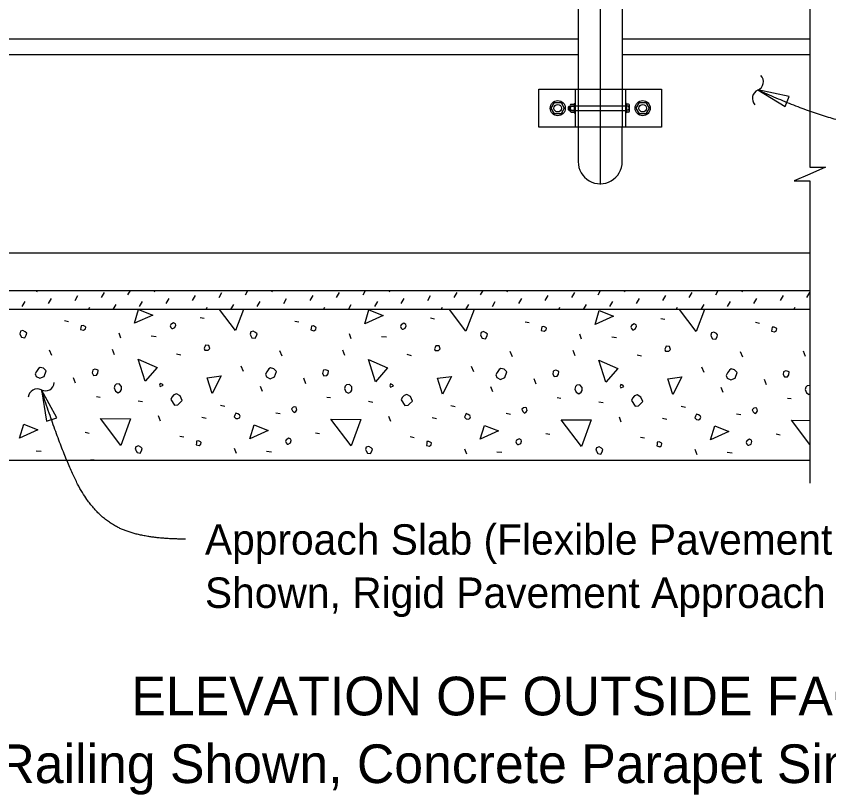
# Model space of a CAD drawing. Extents: x 0 to 41.1, y 0 to 25.9.
# Drawn here: x 10.75 to 16.13, y 11.22 to 16.37 of the extents above; entities that cross this region are included whole.
import ezdxf

# ---------------------------------------------------------------- set-up
doc = ezdxf.new("R2010")
doc.units = 0
for name, color, linetype in [('CL_Major', 7, 'Continuous'), ('Dimension', 7, 'Continuous'), ('Miscellaneous', 7, 'Continuous'), ('SteelMisc', 7, 'Continuous'), ('SteelMisc_h', 7, 'Continuous'), ('SupstrConc', 7, 'Continuous'), ('SupstrConc_h', 7, 'Continuous')]:
    doc.layers.add(name, color=color, linetype=linetype)

msp = doc.modelspace()

# ---------------------------------------------------------------- linework, layer by layer
at = {"layer": 'CL_Major'}
msp.add_line((14.615, 25.0052), (14.615, 15.2584), dxfattribs=at)
at = {"layer": 'Dimension'}
msp.add_lwpolyline([(16.002, 17.2246), (16.002, 15.3737), (16.1053, 15.3737), (16.002, 15.3287), (15.8987, 15.2837), (16.002, 15.2837), (16.002, 13.2829)], dxfattribs=at)
for points in [[(15.6583, 15.8852), (15.8392, 15.7761), (15.865, 15.8418)], [(10.9179, 13.9006), (10.9525, 13.6922), (11.0192, 13.7152)]]:
    msp.add_lwpolyline(points, close=True, dxfattribs=at)
for centre, start, end in [((15.6351, 15.9394), 292.7091, 44.4364), ((15.6811, 15.8294), 112.7091, 224.4364), ((10.944, 13.9535), 243.2317, 354.9589), ((10.8904, 13.847), 63.2317, 174.9589)]:
    msp.add_arc(centre, 0.0596, start, end, dxfattribs=at)
for points in [[(16.9853, 15.6282), (16.9154, 15.6282), (16.2159, 15.6282), (15.6583, 15.8852)], [(11.8715, 12.9128), (11.6062, 12.9128), (11.3076, 13.0373), (11.092, 13.3693), (10.9179, 13.9005)]]:
    msp.add_open_spline(points, degree=2, dxfattribs=at)
at = {"layer": 'Miscellaneous'}
for p, q in [((14.4075, 15.7575), (14.4075, 15.7696)), ((14.4132, 15.7575), (14.4132, 15.7696)), ((10.8876, 14.5495), (10.8924, 14.5578)), ((11.1404, 14.4912), (11.1599, 14.5248)), ((11.3154, 14.5106), (11.3349, 14.5442)), ((11.4904, 14.5301), (11.5065, 14.5578)), ((11.6655, 14.5495), (11.6703, 14.5578)), ((11.9182, 14.4912), (11.9377, 14.5248)), ((12.0933, 14.5106), (12.1127, 14.5442)), ((12.2683, 14.5301), (12.2843, 14.5578)), ((12.4433, 14.5495), (12.4481, 14.5578)), ((12.6961, 14.4912), (12.7155, 14.5248)), ((12.8711, 14.5106), (12.8905, 14.5442)), ((13.0461, 14.5301), (13.0621, 14.5578)), ((13.2211, 14.5495), (13.2259, 14.5578)), ((13.4739, 14.4912), (13.4933, 14.5248)), ((13.6489, 14.5106), (13.6683, 14.5442)), ((13.8239, 14.5301), (13.84, 14.5578)), ((13.9989, 14.5495), (14.0037, 14.5578)), ((14.2517, 14.4912), (14.2711, 14.5248)), ((14.4267, 14.5106), (14.4462, 14.5442)), ((14.6017, 14.5301), (14.6178, 14.5578)), ((14.7767, 14.5495), (14.7815, 14.5578)), ((15.0295, 14.4912), (15.049, 14.5248)), ((15.2045, 14.5106), (15.224, 14.5442)), ((15.3795, 14.5301), (15.3956, 14.5578)), ((15.5545, 14.5495), (15.5593, 14.5578)), ((15.8073, 14.4912), (15.8268, 14.5248)), ((15.9823, 14.5106), (16.0018, 14.5442)), ((10.7904, 14.4523), (10.8099, 14.4859)), ((10.9654, 14.4717), (10.9849, 14.5053)), ((11.3932, 14.4329), (11.4127, 14.4664)), ((11.5682, 14.4523), (11.5877, 14.4859)), ((11.7432, 14.4717), (11.7627, 14.5053)), ((12.171, 14.4329), (12.1905, 14.4664)), ((12.346, 14.4523), (12.3655, 14.4859)), ((12.5211, 14.4717), (12.5405, 14.5053)), ((12.9489, 14.4329), (12.9683, 14.4664)), ((13.1239, 14.4523), (13.1433, 14.4859)), ((13.2989, 14.4717), (13.3183, 14.5053)), ((13.7267, 14.4329), (13.7461, 14.4664)), ((13.9017, 14.4523), (13.9211, 14.4859)), ((14.0767, 14.4717), (14.0961, 14.5053)), ((14.5045, 14.4329), (14.5239, 14.4664)), ((14.6795, 14.4523), (14.6989, 14.4859)), ((14.8545, 14.4717), (14.874, 14.5053)), ((15.2823, 14.4329), (15.3018, 14.4664)), ((15.4573, 14.4523), (15.4768, 14.4859)), ((15.6323, 14.4717), (15.6518, 14.5053)), ((11.2295, 14.4329), (11.2377, 14.447)), ((12.0073, 14.4329), (12.0155, 14.447)), ((12.7851, 14.4329), (12.7933, 14.447)), ((13.5629, 14.4329), (13.5711, 14.447)), ((14.3407, 14.4329), (14.3489, 14.447)), ((15.1186, 14.4329), (15.1267, 14.447)), ((15.8964, 14.4329), (15.9046, 14.447)), ((11.0699, 14.3586), (11.0964, 14.3533)), ((11.9679, 14.3798), (11.9945, 14.3745)), ((12.5937, 14.3551), (12.6202, 14.3498)), ((13.4917, 14.3763), (13.5183, 14.371)), ((15.0156, 14.3728), (15.0421, 14.3674)), ((14.1175, 14.3515), (14.1441, 14.3462)), ((15.6414, 14.348), (15.6679, 14.3427)), ((11.4447, 14.2419), (11.4323, 14.2755)), ((11.6444, 14.2578), (11.6763, 14.2543)), ((12.9685, 14.2384), (12.9561, 14.272)), ((13.1682, 14.2543), (13.2001, 14.2508)), ((14.4923, 14.2349), (14.4799, 14.2685)), ((14.6921, 14.2508), (14.7239, 14.2472)), ((10.9868, 14.127), (10.9727, 14.1624)), ((11.4022, 14.1323), (11.3881, 14.1677)), ((11.8124, 14.1394), (11.8407, 14.1323)), ((12.5106, 14.1235), (12.4965, 14.1589)), ((12.9261, 14.1288), (12.9119, 14.1642)), ((14.0345, 14.12), (14.0203, 14.1553)), ((14.4499, 14.1253), (14.4357, 14.1606)), ((15.5583, 14.1164), (15.5441, 14.1518)), ((15.9737, 14.1217), (15.9596, 14.1571)), ((13.3362, 14.1359), (13.3645, 14.1288)), ((14.86, 14.1323), (14.8883, 14.1253)), ((12.2543, 14.0227), (12.2402, 14.0581)), ((13.7781, 14.0192), (13.764, 14.0546)), ((15.3019, 14.0157), (15.2878, 14.051)), ((11.1442, 13.945), (11.13, 13.9803)), ((12.668, 13.9414), (12.6538, 13.9768)), ((12.3798, 13.8901), (12.3675, 13.9237)), ((14.1918, 13.9379), (14.1776, 13.9732)), ((15.7156, 13.9343), (15.7015, 13.9697)), ((13.9036, 13.8866), (13.8913, 13.9202)), ((15.4275, 13.8831), (15.4151, 13.9167)), ((11.282, 13.8566), (11.3068, 13.853)), ((11.5578, 13.8283), (11.5879, 13.823)), ((12.8059, 13.853), (12.8306, 13.8495)), ((13.0816, 13.8247), (13.1117, 13.8194)), ((14.3297, 13.8495), (14.3544, 13.846)), ((14.6054, 13.8212), (14.6355, 13.8159)), ((15.8535, 13.846), (15.8782, 13.8424)), ((12.1023, 13.8), (12.1306, 13.7929)), ((13.6261, 13.7965), (13.6544, 13.7894)), ((15.1499, 13.7929), (15.1782, 13.7859)), ((11.7063, 13.6939), (11.6939, 13.7275)), ((11.9803, 13.7204), (12.0086, 13.7134)), ((12.4682, 13.7487), (12.4983, 13.7434)), ((13.2301, 13.6904), (13.2177, 13.724)), ((13.5041, 13.7169), (13.5324, 13.7098)), ((13.992, 13.7452), (14.0221, 13.7399)), ((14.7539, 13.6869), (14.7416, 13.7204)), ((15.0279, 13.7134), (15.0562, 13.7063)), ((15.5158, 13.7417), (15.5459, 13.7364)), ((11.2078, 13.6197), (11.2343, 13.6144)), ((12.7316, 13.6161), (12.7581, 13.6108)), ((14.2554, 13.6126), (14.2819, 13.6073)), ((15.7792, 13.6091), (15.8058, 13.6038)), ((11.8336, 13.5949), (11.8601, 13.5896)), ((13.3574, 13.5914), (13.3839, 13.5861)), ((14.8812, 13.5879), (14.9077, 13.5826)), ((10.8843, 13.4977), (10.9161, 13.4942)), ((12.2084, 13.4783), (12.196, 13.5118)), ((12.4081, 13.4942), (12.4399, 13.4906)), ((13.7322, 13.4747), (13.7198, 13.5083)), ((15.256, 13.4712), (15.2436, 13.5048)), ((13.9319, 13.4906), (13.9637, 13.4871)), ((15.4557, 13.4871), (15.4876, 13.4836))]:
    msp.add_line(p, q, dxfattribs=at)
for points in [[(11.5331, 14.3409), (11.5613, 14.4329), (11.655, 14.3957), (11.5331, 14.3409)], [(12.203, 14.2932), (12.0969, 14.4329)], [(12.2552, 14.4329), (12.203, 14.2932)], [(13.0569, 14.3374), (13.0852, 14.4293), (13.1789, 14.3922), (13.0569, 14.3374)], [(13.7269, 14.2897), (13.618, 14.4329)], [(13.7804, 14.4329), (13.7269, 14.2897)], [(14.5807, 14.3339), (14.609, 14.4258), (14.7027, 14.3887), (14.5807, 14.3339)], [(15.2507, 14.2861), (15.1392, 14.4329)], [(15.3055, 14.4329), (15.2507, 14.2861)], [(11.1777, 14.3003), (11.1972, 14.295), (11.2096, 14.3038), (11.2113, 14.3162), (11.2078, 14.3197), (11.1937, 14.3268), (11.1813, 14.325), (11.1795, 14.3126), (11.1777, 14.3003)], [(11.7806, 14.3056), (11.7876, 14.3056), (11.8018, 14.3126), (11.8071, 14.3286), (11.8053, 14.3374), (11.7912, 14.3445), (11.7735, 14.3339), (11.7699, 14.3233), (11.7735, 14.3126), (11.7806, 14.3056)], [(12.7016, 14.2967), (12.721, 14.2914), (12.7334, 14.3003), (12.7351, 14.3126), (12.7316, 14.3162), (12.7175, 14.3233), (12.7051, 14.3215), (12.7033, 14.3091), (12.7016, 14.2967)], [(13.3044, 14.302), (13.3114, 14.302), (13.3256, 14.3091), (13.3309, 14.325), (13.3291, 14.3339), (13.315, 14.3409), (13.2973, 14.3303), (13.2938, 14.3197), (13.2973, 14.3091), (13.3044, 14.302)], [(14.2254, 14.2932), (14.2448, 14.2879), (14.2572, 14.2967), (14.259, 14.3091), (14.2554, 14.3126), (14.2413, 14.3197), (14.2289, 14.3179), (14.2271, 14.3056), (14.2254, 14.2932)], [(14.8282, 14.2985), (14.8353, 14.2985), (14.8494, 14.3056), (14.8547, 14.3215), (14.8529, 14.3303), (14.8388, 14.3374), (14.8211, 14.3268), (14.8176, 14.3162), (14.8211, 14.3056), (14.8282, 14.2985)], [(15.7492, 14.2897), (15.7686, 14.2844), (15.781, 14.2932), (15.7828, 14.3056), (15.7792, 14.3091), (15.7651, 14.3162), (15.7527, 14.3144), (15.751, 14.302), (15.7492, 14.2897)], [(10.7782, 14.2649), (10.7871, 14.249), (10.8083, 14.2455), (10.8171, 14.2614), (10.8207, 14.2755), (10.8118, 14.2844), (10.7959, 14.2932), (10.78, 14.2879), (10.7747, 14.272), (10.7782, 14.2649)], [(12.302, 14.2614), (12.3109, 14.2455), (12.3321, 14.2419), (12.3409, 14.2578), (12.3445, 14.272), (12.3356, 14.2808), (12.3197, 14.2897), (12.3038, 14.2844), (12.2985, 14.2685), (12.302, 14.2614)], [(13.8259, 14.2578), (13.8347, 14.2419), (13.8559, 14.2384), (13.8647, 14.2543), (13.8683, 14.2685), (13.8594, 14.2773), (13.8435, 14.2861), (13.8276, 14.2808), (13.8223, 14.2649), (13.8259, 14.2578)], [(15.3497, 14.2543), (15.3585, 14.2384), (15.3797, 14.2349), (15.3886, 14.2508), (15.3921, 14.2649), (15.3833, 14.2738), (15.3674, 14.2826), (15.3514, 14.2773), (15.3461, 14.2614), (15.3497, 14.2543)], [(11.9998, 14.1642), (12.021, 14.1642), (12.0316, 14.1748), (12.0263, 14.1942), (12.0033, 14.196), (11.9998, 14.1854), (11.9945, 14.1765), (11.9998, 14.1642), (11.9962, 14.1677)], [(13.5236, 14.1606), (13.5448, 14.1606), (13.5554, 14.1712), (13.5501, 14.1907), (13.5271, 14.1924), (13.5236, 14.1818), (13.5183, 14.173), (13.5236, 14.1606), (13.52, 14.1642)], [(15.0474, 14.1571), (15.0686, 14.1571), (15.0792, 14.1677), (15.0739, 14.1871), (15.0509, 14.1889), (15.0474, 14.1783), (15.0421, 14.1695), (15.0474, 14.1571), (15.0438, 14.1606)], [(11.6055, 13.9573), (11.5578, 14.104), (11.6833, 14.0492), (11.6055, 13.9573)], [(13.1294, 13.9538), (13.0816, 14.1005), (13.2071, 14.0457), (13.1294, 13.9538)], [(14.6532, 13.9503), (14.6054, 14.097), (14.731, 14.0422), (14.6532, 13.9503)], [(10.8843, 13.9891), (10.9073, 13.9768), (10.9373, 13.9891), (10.9497, 14.0263), (10.932, 14.0439), (10.909, 14.0492), (10.8984, 14.0422), (10.8861, 14.0227), (10.8772, 14.0068), (10.8843, 13.9891)], [(11.2538, 14.0121), (11.2626, 13.9962), (11.282, 13.998), (11.2909, 14.0104), (11.2926, 14.0298), (11.2803, 14.0351), (11.2714, 14.0369), (11.2608, 14.0333), (11.2573, 14.0298), (11.2538, 14.0121)], [(12.4081, 13.9856), (12.4311, 13.9732), (12.4611, 13.9856), (12.4735, 14.0227), (12.4558, 14.0404), (12.4329, 14.0457), (12.4223, 14.0386), (12.4099, 14.0192), (12.401, 14.0033), (12.4081, 13.9856)], [(12.7776, 14.0086), (12.7864, 13.9927), (12.8059, 13.9944), (12.8147, 14.0068), (12.8165, 14.0263), (12.8041, 14.0316), (12.7952, 14.0333), (12.7846, 14.0298), (12.7811, 14.0263), (12.7776, 14.0086)], [(13.9319, 13.9821), (13.9549, 13.9697), (13.985, 13.9821), (13.9973, 14.0192), (13.9797, 14.0369), (13.9567, 14.0422), (13.9461, 14.0351), (13.9337, 14.0157), (13.9249, 13.9998), (13.9319, 13.9821)], [(14.3014, 14.0051), (14.3102, 13.9891), (14.3297, 13.9909), (14.3385, 14.0033), (14.3403, 14.0227), (14.3279, 14.028), (14.3191, 14.0298), (14.3085, 14.0263), (14.3049, 14.0227), (14.3014, 14.0051)], [(15.4557, 13.9785), (15.4787, 13.9662), (15.5088, 13.9785), (15.5211, 14.0157), (15.5035, 14.0333), (15.4805, 14.0386), (15.4699, 14.0316), (15.4575, 14.0121), (15.4487, 13.9962), (15.4557, 13.9785)], [(12.0475, 13.876), (12.0139, 13.9803), (12.1076, 13.9927), (12.0475, 13.876)], [(13.5713, 13.8725), (13.5377, 13.9768), (13.6314, 13.9891), (13.5713, 13.8725)], [(15.0951, 13.8689), (15.0615, 13.9732), (15.1552, 13.9856), (15.0951, 13.8689)], [(15.8252, 14.0015), (15.834, 13.9856), (15.8535, 13.9874), (15.8623, 13.9998), (15.8641, 14.0192), (15.8517, 14.0245), (15.8429, 14.0263), (15.8323, 14.0227), (15.8287, 14.0192), (15.8252, 14.0015)], [(11.3987, 13.9131), (11.4093, 13.8919), (11.427, 13.8813), (11.4411, 13.8919), (11.4482, 13.9025), (11.4482, 13.9237), (11.4323, 13.9396), (11.4129, 13.9379), (11.404, 13.929), (11.3987, 13.9131)], [(11.7045, 13.922), (11.724, 13.9308), (11.7169, 13.9379), (11.7045, 13.9432), (11.6992, 13.9308), (11.7045, 13.922)], [(12.9225, 13.9096), (12.9331, 13.8884), (12.9508, 13.8778), (12.965, 13.8884), (12.972, 13.899), (12.972, 13.9202), (12.9561, 13.9361), (12.9367, 13.9343), (12.9278, 13.9255), (12.9225, 13.9096)], [(13.2284, 13.9184), (13.2478, 13.9273), (13.2407, 13.9343), (13.2284, 13.9396), (13.223, 13.9273), (13.2284, 13.9184)], [(14.4463, 13.9061), (14.457, 13.8848), (14.4746, 13.8742), (14.4888, 13.8848), (14.4958, 13.8955), (14.4958, 13.9167), (14.4799, 13.9326), (14.4605, 13.9308), (14.4516, 13.922), (14.4463, 13.9061)], [(14.7522, 13.9149), (14.7716, 13.9237), (14.7645, 13.9308), (14.7522, 13.9361), (14.7469, 13.9237), (14.7522, 13.9149)], [(16.002, 13.9289), (15.9843, 13.9273), (15.9755, 13.9184), (15.9702, 13.9025)], [(11.7752, 13.8371), (11.7982, 13.8), (11.8212, 13.8018), (11.83, 13.8106), (11.8495, 13.83), (11.8371, 13.8601), (11.8124, 13.8742), (11.7947, 13.8672), (11.7806, 13.853), (11.7752, 13.8371)], [(13.2991, 13.8336), (13.322, 13.7965), (13.345, 13.7982), (13.3539, 13.8071), (13.3733, 13.8265), (13.3609, 13.8566), (13.3362, 13.8707), (13.3185, 13.8636), (13.3044, 13.8495), (13.2991, 13.8336)], [(15.9702, 13.9025), (15.9808, 13.8813), (15.9984, 13.8707), (16.002, 13.8734)], [(14.8229, 13.83), (14.8459, 13.7929), (14.8688, 13.7947), (14.8777, 13.8035), (14.8971, 13.823), (14.8848, 13.853), (14.86, 13.8672), (14.8423, 13.8601), (14.8282, 13.846), (14.8229, 13.83)], [(12.5796, 13.7611), (12.5902, 13.7505), (12.6008, 13.7576), (12.6079, 13.7682), (12.6043, 13.7859), (12.5955, 13.7876), (12.5831, 13.7859), (12.5725, 13.7752), (12.5796, 13.7611)], [(14.1034, 13.7576), (14.114, 13.747), (14.1246, 13.754), (14.1317, 13.7646), (14.1281, 13.7823), (14.1193, 13.7841), (14.1069, 13.7823), (14.0963, 13.7717), (14.1034, 13.7576)], [(15.6272, 13.754), (15.6378, 13.7434), (15.6484, 13.7505), (15.6555, 13.7611), (15.652, 13.7788), (15.6431, 13.7805), (15.6307, 13.7788), (15.6201, 13.7682), (15.6272, 13.754)], [(11.4429, 13.5331), (11.3086, 13.7098), (11.5083, 13.7081), (11.4429, 13.5331)], [(12.2048, 13.7116), (12.2172, 13.7098), (12.2296, 13.7151), (12.2331, 13.7257), (12.2278, 13.7346), (12.2172, 13.7417), (12.2048, 13.747), (12.1977, 13.7328), (12.1942, 13.7222), (12.2048, 13.7116)], [(13.7286, 13.7081), (13.741, 13.7063), (13.7534, 13.7116), (13.7569, 13.7222), (13.7516, 13.7311), (13.741, 13.7381), (13.7286, 13.7434), (13.7216, 13.7293), (13.718, 13.7187), (13.7286, 13.7081)], [(15.2524, 13.7045), (15.2648, 13.7028), (15.2772, 13.7081), (15.2807, 13.7187), (15.2754, 13.7275), (15.2648, 13.7346), (15.2524, 13.7399), (15.2454, 13.7257), (15.2418, 13.7151), (15.2524, 13.7045)], [(10.7729, 13.5808), (10.8012, 13.6727), (10.8949, 13.6356), (10.7729, 13.5808)], [(12.2967, 13.5773), (12.325, 13.6692), (12.4187, 13.6321), (12.2967, 13.5773)], [(12.9667, 13.5295), (12.8324, 13.7063), (13.0321, 13.7045), (12.9667, 13.5295)], [(13.8206, 13.5737), (13.8488, 13.6656), (13.9425, 13.6285), (13.8206, 13.5737)], [(14.4905, 13.526), (14.3562, 13.7028), (14.5559, 13.701), (14.4905, 13.526)], [(15.3444, 13.5702), (15.3727, 13.6621), (15.4663, 13.625), (15.3444, 13.5702)], [(16.002, 13.5387), (15.88, 13.6992), (16.002, 13.6982)], [(11.9414, 13.5366), (11.9609, 13.5313), (11.9732, 13.5401), (11.975, 13.5525), (11.9715, 13.556), (11.9573, 13.5631), (11.945, 13.5613), (11.9432, 13.549), (11.9414, 13.5366)], [(12.5442, 13.5419), (12.5513, 13.5419), (12.5654, 13.549), (12.5707, 13.5649), (12.569, 13.5737), (12.5548, 13.5808), (12.5372, 13.5702), (12.5336, 13.5596), (12.5372, 13.549), (12.5442, 13.5419)], [(13.4652, 13.5331), (13.4847, 13.5278), (13.4971, 13.5366), (13.4988, 13.549), (13.4953, 13.5525), (13.4811, 13.5596), (13.4688, 13.5578), (13.467, 13.5454), (13.4652, 13.5331)], [(14.068, 13.5384), (14.0751, 13.5384), (14.0893, 13.5454), (14.0946, 13.5613), (14.0928, 13.5702), (14.0786, 13.5773), (14.061, 13.5666), (14.0574, 13.556), (14.061, 13.5454), (14.068, 13.5384)], [(14.989, 13.5295), (15.0085, 13.5242), (15.0209, 13.5331), (15.0226, 13.5454), (15.0191, 13.549), (15.005, 13.556), (14.9926, 13.5543), (14.9908, 13.5419), (14.989, 13.5295)], [(15.5919, 13.5348), (15.5989, 13.5348), (15.6131, 13.5419), (15.6184, 13.5578), (15.6166, 13.5666), (15.6025, 13.5737), (15.5848, 13.5631), (15.5813, 13.5525), (15.5848, 13.5419), (15.5919, 13.5348)], [(11.5419, 13.5012), (11.5507, 13.4853), (11.572, 13.4818), (11.5808, 13.4977), (11.5843, 13.5118), (11.5755, 13.5207), (11.5596, 13.5295), (11.5437, 13.5242), (11.5384, 13.5083), (11.5419, 13.5012)], [(13.0657, 13.4977), (13.0746, 13.4818), (13.0958, 13.4783), (13.1046, 13.4942), (13.1081, 13.5083), (13.0993, 13.5172), (13.0834, 13.526), (13.0675, 13.5207), (13.0622, 13.5048), (13.0657, 13.4977)], [(14.5895, 13.4942), (14.5984, 13.4783), (14.6196, 13.4747), (14.6284, 13.4906), (14.632, 13.5048), (14.6231, 13.5136), (14.6072, 13.5225), (14.5913, 13.5172), (14.586, 13.5012), (14.5895, 13.4942)], [(11.2665, 13.4328), (11.2661, 13.4341), (11.2432, 13.4358), (11.2422, 13.4328)]]:
    msp.add_lwpolyline(points, dxfattribs=at)
at = {"layer": 'SteelMisc'}
for p, q in [((14.4692, 16.6394), (14.4692, 15.8894)), ((14.7609, 16.6394), (14.7609, 15.8894)), ((14.2091, 15.8894), (15.021, 15.8894)), ((14.2091, 15.6394), (14.2091, 15.8894)), ((14.4484, 15.8894), (14.4484, 15.6394)), ((14.7817, 15.8894), (14.7817, 15.6394)), ((15.021, 15.8894), (15.021, 15.6394)), ((14.4047, 15.7724), (14.4103, 15.7789)), ((14.4047, 15.7547), (14.4047, 15.7724)), ((14.4047, 15.7547), (14.4103, 15.749)), ((14.4103, 15.7789), (14.4168, 15.7789)), ((14.4103, 15.749), (14.4103, 15.7789)), ((14.4168, 15.7823), (14.4168, 15.7465)), ((14.4215, 15.7774), (14.4418, 15.7774)), ((14.4215, 15.7514), (14.4418, 15.7514)), ((14.4217, 15.7904), (14.4418, 15.7904)), ((14.4418, 15.7947), (14.4418, 15.734)), ((14.4418, 15.7947), (14.4484, 15.7947)), ((14.4418, 15.7904), (14.4418, 15.7384)), ((14.788, 15.7947), (14.782, 15.7947)), ((14.788, 15.7947), (14.788, 15.734)), ((14.8027, 15.7903), (14.788, 15.7903)), ((14.8028, 15.7773), (14.788, 15.7773)), ((14.8028, 15.7514), (14.788, 15.7514)), ((14.8078, 15.745), (14.8078, 15.7838)), ((14.4103, 15.749), (14.4168, 15.749)), ((14.4218, 15.7384), (14.4418, 15.7384)), ((14.4418, 15.734), (14.4484, 15.734)), ((14.788, 15.734), (14.782, 15.734)), ((14.8027, 15.7384), (14.788, 15.7384)), ((15.021, 15.6394), (14.2091, 15.6394)), ((14.4691, 15.6394), (14.4691, 15.4102)), ((14.7608, 15.4102), (14.7608, 15.6394))]:
    msp.add_line(p, q, dxfattribs=at)
for points in [[(14.3124, 15.8019), (14.3557, 15.8019), (14.3774, 15.7644), (14.3557, 15.7269), (14.3124, 15.7269), (14.2907, 15.7644)], [(14.8744, 15.8019), (14.9177, 15.8019), (14.9394, 15.7644), (14.9177, 15.7269), (14.8744, 15.7269), (14.8527, 15.7644)]]:
    msp.add_lwpolyline(points, close=True, dxfattribs=at)
for centre, radius in [((14.3341, 15.7644), 0.05), ((14.896, 15.7644), 0.05), ((14.3341, 15.7644), 0.025), ((14.896, 15.7644), 0.025)]:
    msp.add_circle(centre, radius, dxfattribs=at)
for centre, radius, start, end in [((14.4234, 15.7838), 0.00674, 104.4891, 254.1889), ((14.4363, 15.7644), 0.0196, 138.628, 221.372), ((14.4234, 15.7449), 0.00673, 105.7823, 255.5404), ((14.801, 15.7838), 0.00673, 285.7823, 75.5404), ((14.801, 15.7449), 0.00674, 284.4891, 74.1889), ((14.7881, 15.7644), 0.0196, 318.628, 41.372)]:
    msp.add_arc(centre, radius, start, end, dxfattribs=at)
msp.add_ellipse((14.615, 15.4102), major_axis=(0, 0.1458), ratio=0.999499, start_param=1.570796, end_param=4.712389, dxfattribs=at)
at = {"layer": 'SteelMisc_h'}
for p, q in [((14.4692, 15.8894), (14.4692, 15.6394)), ((14.7609, 15.8894), (14.7609, 15.6394)), ((14.7817, 15.7789), (14.4168, 15.7789)), ((14.4168, 15.749), (14.7817, 15.749))]:
    msp.add_line(p, q, dxfattribs=at)
at = {"layer": 'SupstrConc'}
for p, q in [((4.7609, 16.2245), (14.4692, 16.2245)), ((14.7609, 16.2245), (16.002, 16.2245)), ((4.7609, 16.1203), (14.4692, 16.1203)), ((14.7609, 16.1203), (16.002, 16.1203)), ((3.615, 14.5578), (16.002, 14.5578)), ((16.002, 14.4329), (3.615, 14.4329)), ((16.002, 13.4328), (3.615, 13.4328))]:
    msp.add_line(p, q, dxfattribs=at)
at = {"layer": 'SupstrConc_h'}
msp.add_line((3.615, 14.8078), (16.002, 14.8078), dxfattribs=at)

# ---------------------------------------------------------------- texts
at = {"layer": 'Dimension'}
for s, height, p in [('Approach Slab (Flexible Pavement Approach Slab ', 0.2016, (11.9999, 12.8093)), ('Shown, Rigid Pavement Approach Slab Similar)', 0.2016, (11.9999, 12.4573)), ('ELEVATION OF OUTSIDE FACE OF RAILING', 0.256001, (11.5134, 11.7461)), ('(Traffic Railing Shown, Concrete Parapet Similar (See Note 3))', 0.256001, (9.4668, 11.2981))]:
    msp.add_text(s, height=height, dxfattribs=at).set_placement(p)

doc.saveas('drawing.dxf')
